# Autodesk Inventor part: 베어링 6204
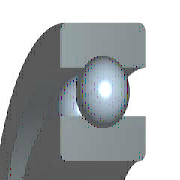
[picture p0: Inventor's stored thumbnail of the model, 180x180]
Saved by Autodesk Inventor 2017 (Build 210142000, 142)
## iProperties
IsCustomPart: 0
Created: 2018-09
Part Number: 베어링 6204
Material: 스테인리스강
Description: 깊은 그루브 볼 베어링
Document SubType Name: Modeling
Standard: KS B 2023
Standards Organization: KS
Language: ko-KR
Size Designation: 6204 - 20 x 47 x 14
Categories: <MemberInstance><Categories><Category DisplayName="샤프트 부품" InternalName="7f7aeb1f-a693-4053-b835-cee3144e0d98" Mnemonic="SHFT"><Category DisplayName="베어링" Inter
Density: 8.08 g/cm^3
Mass: 107.173 g
Surface Area: 87.8912 cm^2
Volume: 13.264 cm^3
Appearance: 노란색
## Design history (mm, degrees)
sketch "스케치" dims "d0" = 7.02 (= -0.26 x WD + 0.26 x BD)
  geometry: L1 (3.49, 16.75)-(10.51, 16.75); L2 (7, 16.75)-(7, 13.24); L3 (7, 16.75)-(7, 20.26); L4 (4.392, 14.401)-(0, 14.401); L5 (0, 10)-(14, 10); L6 (4.392, 19.099)-(0, 19.099); L7 (0, 23.5)-(14, 23.5); L8 (14, 10)-(14, 14.401); L9 (9.608, 14.401)-(14, 14.401); L10 (9.608, 19.099)-(14, 19.099); L11 (14, 23.5)-(14, 19.099); L12 (-1.4, 0)-(8.4, 0) reference; L13 (0, -0.3)-(0, 5.3) reference
  constraints: 22 end point, 4 point on line, 2 collinear, 2 perpendicular, 2 symmetric about line, 1 midpoint, 1 parallel, 14 other
  dimensions: "d9" = 20 diameter of L5 L12 (= WD); "d11" = 47 diameter of L7 L12 (= BD); "d12" = 14 distance between parallel lines of L8 L13 (= KB); "d13" = 28.802 diameter of L9 L12 (= 0.326 x BD + 0.674 x WD)
revolve "본체" stored, may be unused: angle "d6" = 90 deg
revolve "볼" stored, may be unused: angle "d7" = 90 deg
pattern_circular "IDS_ARRAYBALL[SIMPL:T]" dims angle "d3" = 360 deg
body "Solid1"
fillet "모깎기1" dims "d1" = 1 (= KRS)
other parameters: "WD" = 20 [user parameter; used in 5 equation terms], "BD" = 47 [user parameter; used in 5 equation terms], "KB" = 14 [user parameter; used in 1 equation term], "KRS" = 1 [user parameter; used in 1 equation term], "d4" = 0, "d5" = 0, "d8" = 0, "d14" = 0, "d15" = 0, "BBA" = 0 [user parameter], "BC0" = 6550000 [user parameter], "BC" = 1.27e+07 [user parameter], "BR" = 23.5 (= 0.5 x BD) [user parameter]
